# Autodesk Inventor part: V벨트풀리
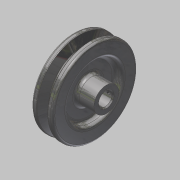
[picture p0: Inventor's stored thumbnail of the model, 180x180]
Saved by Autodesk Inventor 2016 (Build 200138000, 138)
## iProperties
Created: 2015-11
Part Number: V벨트풀리
Material: 강철, 탄소
Document SubType Name: Modeling
Designer: mduedu
Density: 1 g/cm^3
Appearance: 반광택
Author: mduedu
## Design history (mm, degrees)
sketch "스케치1"
  geometry: L1 (-9.5, 0)-(9.5, 0); L2 (0, 0)-(0, 37.7); L3 (-4.825, 37.7)-(-9.5, 37.7); L4 (-9.5, 37.7)-(-9.5, 0); L5 (0, 28.7)-(-2.074, 28.7); L6 (-2.074, 28.7)-(-4.825, 37.7); L7 (4.825, 37.7)-(9.5, 37.7); L8 (9.5, 37.7)-(9.5, 0); L9 (0, 28.7)-(2.074, 28.7); L10 (2.074, 28.7)-(4.825, 37.7); L11 (-9.5, 35)-(9.5, 35); 3 further points
  constraints: 22 end point, 7 point on line, 4 perpendicular, 3 symmetric about line, 1 coincident, 1 horizontal, 1 horizontal alignment, 1 midpoint, 1 vertical
  dimensions: "d0" = 19 distance of L1.start L1.end; "d2" = 75.4 diameter of L2.end L1 (derived); "d3" = 34 deg angle of L10 L6; "d4" = 6.3 distance between parallel lines of L11 L9; "d5" = 2.7 distance between parallel lines of L7 L11; "d6" = 8 distance of point (4, 35) point (-4, 35); "d7" = 70 diameter of L11 L1
revolve "회전1" sketch "스케치1" stored, may be unused: angle "d8" = 90 deg
sketch "스케치2"
  geometry: C1 r 24 at (0, 0); C2 r 11 at (0, 0); 1 further point
  constraints: 2 centre point, 2 coincident
  dimensions: "d9" = 48 diameter of C1; "d10" = 22 diameter of C2
extrude "돌출1" cut sketch "스케치2" distance "d11" = 6; taper "d12" = 0 deg
extrude "돌출3" join sketch "스케치2" distance "d37" = 10; taper "d38" = 0 deg
fillet "모깎기1" dims "d13" = 3
fillet "모깎기2" dims "d14" = 3
fillet "모깎기3" dims "d15" = 1, "d16" = 0.5, "d17" = 2
hole "구멍1" diameter "d20" = 12; stored, may be unused: countersink angle "d24" = 90 deg, drill point angle "d26" = 118 deg; dims "d21" = 6, "d22" = 4, "d23" = 2, "d25" = 8, "d39" = 10, "d40" = 10
sketch "스케치3"
  geometry: L1 (-2, 0)-(2, 0); L2 (2, 0)-(2, 7.8); L3 (2, 7.8)-(-2, 7.8); L4 (-2, 7.8)-(-2, 0); 2 further points
  constraints: 8 end point, 2 parallel, 1 coincident, 1 horizontal, 1 midpoint, 1 perpendicular
  dimensions: "d27" = 4 distance of L2.end L3.end; "d29" = 7.8 distance of L3.end L1.start
extrude "돌출2" cut sketch "스케치3" stored distance "d30" = 6; taper "d31" = 0 deg
chamfer "모따기1" distance "d32" = 1; stored, may be unused: second distance "d33" = 2, angle "d34" = 45 deg
node "작업 평면1"
sketch "스케치4"
  geometry: L1 (-19, 11)-(-19, -11) reference; 2 further points
  constraints: 1 horizontal alignment
  dimensions: "d41" = 25 distance from line of point (6, 0) L1
hole "구멍2" sketch "스케치4" at (6, 0) diameter "d42" = 2.459; stored, may be unused: countersink angle "d46" = 90 deg, drill point angle "d48" = 118 deg; dims "d43" = 6, "d44" = 4, "d45" = 2, "d47" = 8
chamfer "모따기2" distance "d49" = 1; stored, may be unused: second distance "d50" = 2, angle "d51" = 45 deg
node "솔리드1"
mirror "대칭1"
